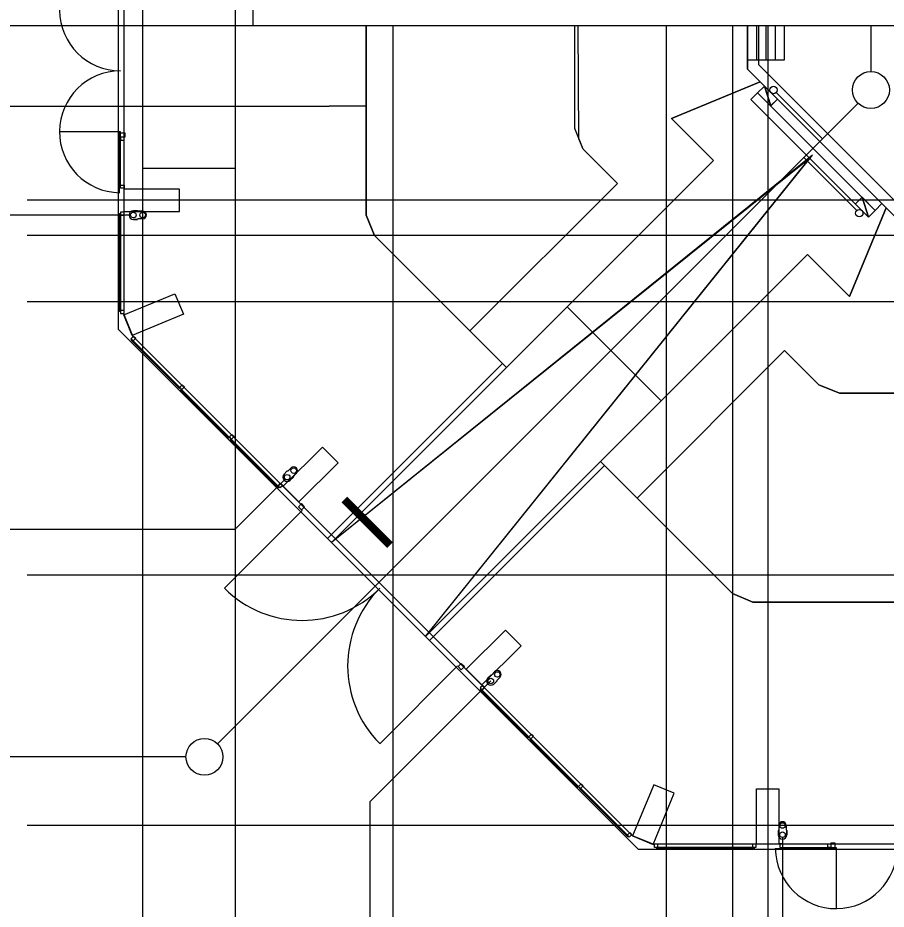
# Model space of a CAD drawing. Extents: x -264205 to -263659, y -1242401 to -1241986.
# Drawn here: x -263911.77 to -263888.26, y -1242243.07 to -1242218.94 of the extents above; entities that cross this region are included whole.
import ezdxf

# ---------------------------------------------------------------- set-up
doc = ezdxf.new("R2010")
doc.units = 0
for name, color, linetype in [('HESCON_OSI_STAVBY_KFA', 7, 'Continuous'), ('PROJEKT_OBRUBNIKY_KOMUNIKACIE', 7, 'Continuous'), ('RAM_NA_TLAC_2-1_1-250', 7, 'Continuous'), ('RAM_NA_TLAC_2-3_1-250', 7, 'Continuous'), ('SITUACIA_DSP_2D', 7, 'Continuous')]:
    doc.layers.add(name, color=color, linetype=linetype)

msp = doc.modelspace()

# ---------------------------------------------------------------- linework, layer by layer
at = {"layer": 'HESCON_OSI_STAVBY_KFA'}
for p, q in [((-263908.393, -1242083.237), (-263908.393, -1242246.707)), ((-263901.618, -1242219.157), (-263901.618, -1242246.707)), ((-263894.218, -1242219.157), (-263894.218, -1242246.707)), ((-263892.418, -1242219.157), (-263892.418, -1242246.707)), ((-263891.468, -1242219.157), (-263891.468, -1242246.707)), ((-263792.653, -1242223.882), (-263911.523, -1242223.882)), ((-263792.653, -1242224.832), (-263911.523, -1242224.832)), ((-263792.653, -1242226.632), (-263911.523, -1242226.632)), ((-263792.653, -1242234.032), (-263911.523, -1242234.032)), ((-263792.653, -1242240.807), (-263911.523, -1242240.807))]:
    msp.add_line(p, q, dxfattribs=at)
at = {"layer": 'PROJEKT_OBRUBNIKY_KOMUNIKACIE'}
for points in [[(-263794.893, -1242227.382), (-263808.968, -1242241.457), (-263894.968, -1242241.457), (-263909.043, -1242227.382), (-263909.043, -1242196.333), (-263914.143, -1242196.333), (-263914.143, -1242132.433), (-263909.043, -1242132.433), (-263909.043, -1242101.382), (-263894.968, -1242087.307), (-263808.968, -1242087.307), (-263794.893, -1242101.382), (-263794.893, -1242227.382)], [(-263898.543, -1242228.407), (-263902.112, -1242224.837), (-263902.343, -1242224.282), (-263902.343, -1242219.157)], [(-263891.673, -1242220.675), (-263894.073, -1242221.669), (-263892.937, -1242222.806), (-263898.544, -1242228.407)], [(-263895.995, -1242230.956), (-263890.391, -1242225.352), (-263889.254, -1242226.488), (-263888.26, -1242224.088), (-263891.673, -1242220.675)], [(-263903.277, -1242233.148), (-263900.731, -1242235.694), (-263890.254, -1242222.659), (-263903.277, -1242233.148)], [(-263898.65, -1242228.301), (-263903.39, -1242233.035), (-263900.629, -1242235.796), (-263895.875, -1242231.049)], [(-263898.544, -1242228.407), (-263903.281, -1242233.144), (-263900.731, -1242235.694), (-263895.982, -1242230.943)], [(-263807.941, -1242230.956), (-263811.512, -1242234.526), (-263812.068, -1242234.757), (-263891.868, -1242234.757), (-263892.424, -1242234.526), (-263895.994, -1242230.956)]]:
    msp.add_lwpolyline(points, dxfattribs=at)
at = {"layer": 'RAM_NA_TLAC_2-1_1-250'}
msp.add_line((-263905.413, -1242216.657), (-263905.413, -1242219.157), dxfattribs=at)
msp.add_lwpolyline([(-264147.913, -1242144.907), (-263857.913, -1242144.907), (-263857.913, -1242219.157), (-264147.913, -1242219.157)], close=True, dxfattribs=at)
at = {"layer": 'RAM_NA_TLAC_2-3_1-250'}
msp.add_line((-263908.389, -1242223.011), (-263905.889, -1242223.011), dxfattribs=at)
msp.add_lwpolyline([(-263980.139, -1242275.511), (-263980.139, -1241985.511), (-263905.889, -1241985.511), (-263905.889, -1242275.511)], close=True, dxfattribs=at)
at = {"layer": 'SITUACIA_DSP_2D'}
for p, q in [((-263909.043, -1242227.382), (-263909.043, -1242196.333)), ((-263908.893, -1242226.995), (-263908.893, -1242203.332)), ((-263902.343, -1242219.157), (-263902.343, -1242224.282)), ((-263902.343, -1242219.157), (-263902.343, -1242224.282)), ((-263902.343, -1242224.282), (-263902.343, -1242219.157)), ((-263896.693, -1242221.942), (-263896.693, -1242219.157)), ((-263896.578, -1242222.219), (-263896.603, -1242219.157)), ((-263892.018, -1242220.33), (-263892.018, -1242219.157)), ((-263892.018, -1242219.157), (-263892.018, -1242220.33)), ((-263891.768, -1242219.157), (-263891.768, -1242220.091)), ((-263891.718, -1242219.157), (-263891.718, -1242220.206)), ((-263891.518, -1242219.157), (-263891.518, -1242220.091)), ((-263891.268, -1242219.157), (-263891.268, -1242220.091)), ((-263891.018, -1242219.157), (-263891.018, -1242220.091)), ((-263888.673, -1242219.157), (-263888.673, -1242220.396)), ((-263891.018, -1242220.091), (-263892.018, -1242220.091)), ((-263891.718, -1242220.206), (-263887.792, -1242224.132)), ((-263891.673, -1242220.675), (-263892.018, -1242220.33)), ((-263892.018, -1242220.33), (-263887.916, -1242224.432)), ((-263894.073, -1242221.669), (-263891.673, -1242220.675)), ((-263891.673, -1242220.675), (-263894.073, -1242221.669)), ((-263888.26, -1242224.088), (-263891.673, -1242220.675)), ((-263891.742, -1242220.974), (-263891.558, -1242220.79)), ((-263891.558, -1242220.79), (-263891.204, -1242221.144)), ((-263888.376, -1242223.973), (-263891.558, -1242220.79)), ((-263891.387, -1242221.326), (-263891.558, -1242220.79)), ((-263891.924, -1242221.157), (-263891.74, -1242220.973)), ((-263891.924, -1242221.157), (-263888.742, -1242224.339)), ((-263888.558, -1242224.155), (-263891.74, -1242220.973)), ((-263891.388, -1242221.328), (-263891.204, -1242221.144)), ((-263891.24, -1242220.967), (-263889.988, -1242222.219)), ((-263923.393, -1242221.332), (-263903.343, -1242221.332)), ((-263889.023, -1242221.253), (-263906.365, -1242238.596)), ((-263902.343, -1242221.332), (-263903.343, -1242221.332)), ((-263892.937, -1242222.806), (-263894.073, -1242221.669)), ((-263894.073, -1242221.669), (-263892.937, -1242222.806)), ((-263908.993, -1242222.027), (-263910.643, -1242222.027)), ((-263909.018, -1242223.677), (-263909.018, -1242222.027)), ((-263908.993, -1242222.052), (-263908.993, -1242222.027)), ((-263908.993, -1242222.052), (-263908.873, -1242222.052)), ((-263908.993, -1242222.172), (-263908.993, -1242222.052)), ((-263908.873, -1242222.052), (-263908.873, -1242222.172)), ((-263896.463, -1242222.496), (-263896.693, -1242221.942)), ((-263909.018, -1242222.212), (-263909.018, -1242223.512)), ((-263908.993, -1242222.212), (-263909.018, -1242222.212)), ((-263908.893, -1242222.172), (-263908.993, -1242222.172)), ((-263908.993, -1242222.172), (-263908.993, -1242222.212)), ((-263908.873, -1242222.172), (-263908.993, -1242222.172)), ((-263908.993, -1242223.512), (-263908.993, -1242222.212)), ((-263908.993, -1242222.212), (-263908.993, -1242222.252)), ((-263908.993, -1242222.252), (-263908.893, -1242222.252)), ((-263908.893, -1242222.252), (-263908.893, -1242222.172)), ((-263896.463, -1242222.496), (-263896.578, -1242222.219)), ((-263895.535, -1242223.424), (-263896.463, -1242222.496)), ((-263895.535, -1242223.424), (-263896.463, -1242222.496)), ((-263890.333, -1242222.748), (-263903.277, -1242233.148)), ((-263900.731, -1242235.694), (-263890.333, -1242222.748)), ((-263892.937, -1242222.806), (-263898.544, -1242228.407)), ((-263896.896, -1242226.765), (-263892.937, -1242222.806)), ((-263889.059, -1242224.16), (-263890.494, -1242222.725)), ((-263909.018, -1242223.512), (-263908.993, -1242223.512)), ((-263908.993, -1242223.512), (-263908.993, -1242223.472)), ((-263908.993, -1242223.472), (-263908.893, -1242223.472)), ((-263908.993, -1242223.552), (-263908.993, -1242223.512)), ((-263908.893, -1242223.552), (-263908.993, -1242223.552)), ((-263907.398, -1242223.582), (-263908.898, -1242223.582)), ((-263908.898, -1242223.582), (-263908.898, -1242224.182)), ((-263908.893, -1242223.472), (-263908.893, -1242223.552)), ((-263907.398, -1242224.182), (-263907.398, -1242223.582)), ((-263899.53, -1242227.419), (-263895.535, -1242223.424)), ((-263899.53, -1242227.419), (-263895.535, -1242223.424)), ((-263889.096, -1242223.985), (-263888.912, -1242223.801)), ((-263888.742, -1242224.339), (-263888.912, -1242223.801)), ((-263888.26, -1242224.088), (-263889.254, -1242226.488)), ((-263889.254, -1242226.488), (-263888.26, -1242224.088)), ((-263888.56, -1242224.156), (-263888.376, -1242223.973)), ((-263908.718, -1242224.282), (-263918.67, -1242224.282)), ((-263909.018, -1242226.892), (-263909.018, -1242224.242)), ((-263909.018, -1242224.242), (-263908.993, -1242224.242)), ((-263908.893, -1242224.202), (-263908.993, -1242224.202)), ((-263908.993, -1242224.202), (-263908.993, -1242224.242)), ((-263908.993, -1242224.242), (-263908.993, -1242226.892)), ((-263908.993, -1242224.242), (-263908.993, -1242224.282)), ((-263908.993, -1242224.282), (-263908.893, -1242224.282)), ((-263908.898, -1242224.182), (-263907.398, -1242224.182)), ((-263908.893, -1242224.282), (-263908.893, -1242224.202)), ((-263908.532, -1242224.165), (-263908.643, -1242224.165)), ((-263908.518, -1242224.179), (-263908.532, -1242224.165)), ((-263908.393, -1242224.179), (-263908.518, -1242224.179)), ((-263902.343, -1242224.282), (-263902.113, -1242224.837)), ((-263902.343, -1242224.282), (-263902.113, -1242224.837)), ((-263902.112, -1242224.837), (-263902.343, -1242224.282)), ((-263888.742, -1242224.339), (-263888.558, -1242224.155)), ((-263908.643, -1242224.399), (-263908.532, -1242224.399)), ((-263908.532, -1242224.399), (-263908.643, -1242224.399)), ((-263908.518, -1242224.385), (-263908.532, -1242224.399)), ((-263908.393, -1242224.385), (-263908.518, -1242224.385)), ((-263902.113, -1242224.837), (-263899.53, -1242227.419)), ((-263902.113, -1242224.837), (-263899.53, -1242227.419)), ((-263898.543, -1242228.407), (-263902.112, -1242224.837)), ((-263895.995, -1242230.956), (-263890.391, -1242225.352)), ((-263890.391, -1242225.351), (-263894.351, -1242229.311)), ((-263889.254, -1242226.488), (-263890.391, -1242225.351)), ((-263890.391, -1242225.352), (-263889.254, -1242226.488)), ((-263908.903, -1242226.985), (-263907.518, -1242226.411)), ((-263907.518, -1242226.411), (-263907.288, -1242226.966)), ((-263908.993, -1242226.892), (-263909.018, -1242226.892)), ((-263908.893, -1242226.865), (-263908.993, -1242226.865)), ((-263908.993, -1242226.865), (-263908.993, -1242226.905)), ((-263908.993, -1242226.905), (-263908.993, -1242226.945)), ((-263908.993, -1242226.945), (-263908.893, -1242226.945)), ((-263908.674, -1242227.54), (-263908.903, -1242226.985)), ((-263908.893, -1242226.945), (-263908.893, -1242226.865)), ((-263907.288, -1242226.966), (-263908.674, -1242227.54)), ((-263894.351, -1242229.311), (-263896.896, -1242226.765)), ((-263908.893, -1242226.995), (-263908.663, -1242227.55)), ((-263894.968, -1242241.457), (-263909.043, -1242227.382)), ((-263908.709, -1242227.631), (-263908.638, -1242227.56)), ((-263908.68, -1242227.659), (-263908.709, -1242227.631)), ((-263908.685, -1242227.654), (-263908.703, -1242227.672)), ((-263908.703, -1242227.672), (-263907.395, -1242228.98)), ((-263907.377, -1242228.963), (-263908.685, -1242227.654)), ((-263908.652, -1242227.688), (-263908.68, -1242227.659)), ((-263908.663, -1242227.55), (-263895.135, -1242241.078)), ((-263908.581, -1242227.617), (-263908.652, -1242227.688)), ((-263908.638, -1242227.56), (-263908.581, -1242227.617)), ((-263895.005, -1242231.945), (-263891.01, -1242227.95)), ((-263891.01, -1242227.95), (-263895.005, -1242231.945)), ((-263891.01, -1242227.95), (-263890.082, -1242228.878)), ((-263890.082, -1242228.878), (-263891.01, -1242227.95)), ((-263898.65, -1242228.301), (-263903.39, -1242233.035)), ((-263898.544, -1242228.407), (-263903.281, -1242233.144)), ((-263907.39, -1242228.95), (-263907.319, -1242228.879)), ((-263907.319, -1242228.879), (-263907.262, -1242228.936)), ((-263890.082, -1242228.878), (-263889.528, -1242229.107)), ((-263889.528, -1242229.107), (-263890.082, -1242228.878)), ((-263907.395, -1242228.98), (-263907.377, -1242228.963)), ((-263907.361, -1242228.978), (-263907.39, -1242228.95)), ((-263907.363, -1242229.012), (-263907.345, -1242228.994)), ((-263906.055, -1242230.32), (-263907.363, -1242229.012)), ((-263907.333, -1242229.007), (-263907.361, -1242228.978)), ((-263907.345, -1242228.994), (-263906.037, -1242230.303)), ((-263907.262, -1242228.936), (-263907.333, -1242229.007)), ((-263889.528, -1242229.107), (-263874.98, -1242229.107)), ((-263874.98, -1242229.107), (-263889.528, -1242229.107)), ((-263906.037, -1242230.303), (-263906.055, -1242230.32)), ((-263906.046, -1242230.294), (-263905.975, -1242230.223)), ((-263906.017, -1242230.322), (-263906.046, -1242230.294)), ((-263906.019, -1242230.356), (-263906.001, -1242230.338)), ((-263904.711, -1242231.664), (-263906.019, -1242230.356)), ((-263905.989, -1242230.351), (-263906.017, -1242230.322)), ((-263906.001, -1242230.338), (-263904.693, -1242231.647)), ((-263905.918, -1242230.28), (-263905.989, -1242230.351)), ((-263905.975, -1242230.223), (-263905.918, -1242230.28)), ((-263903.526, -1242230.561), (-263904.586, -1242231.622)), ((-263903.101, -1242230.985), (-263903.526, -1242230.561)), ((-263904.162, -1242232.046), (-263903.101, -1242230.985)), ((-263900.731, -1242235.694), (-263895.982, -1242230.943)), ((-263900.629, -1242235.796), (-263895.875, -1242231.049)), ((-263892.424, -1242234.526), (-263895.994, -1242230.956)), ((-263904.484, -1242231.218), (-263904.563, -1242231.296)), ((-263904.465, -1242231.218), (-263904.484, -1242231.218)), ((-263904.376, -1242231.13), (-263904.465, -1242231.218)), ((-263904.231, -1242231.275), (-263904.319, -1242231.364)), ((-263904.533, -1242231.432), (-263905.894, -1242232.793)), ((-263904.726, -1242231.613), (-263904.656, -1242231.543)), ((-263904.656, -1242231.543), (-263904.599, -1242231.599)), ((-263904.397, -1242231.462), (-263904.319, -1242231.383)), ((-263904.319, -1242231.383), (-263904.397, -1242231.462)), ((-263904.319, -1242231.364), (-263904.319, -1242231.383)), ((-263904.698, -1242231.642), (-263904.726, -1242231.613)), ((-263904.693, -1242231.647), (-263904.711, -1242231.664)), ((-263904.67, -1242231.67), (-263904.698, -1242231.642)), ((-263904.599, -1242231.599), (-263904.67, -1242231.67)), ((-263904.586, -1242231.622), (-263904.162, -1242232.046)), ((-263892.422, -1242234.528), (-263895.005, -1242231.945)), ((-263895.005, -1242231.945), (-263892.422, -1242234.528)), ((-263904.074, -1242232.281), (-263906.177, -1242234.384)), ((-263904.091, -1242232.093), (-263904.176, -1242232.178)), ((-263904.176, -1242232.178), (-263904.091, -1242232.263)), ((-263904.006, -1242232.178), (-263904.091, -1242232.093)), ((-263904.091, -1242232.263), (-263904.006, -1242232.178)), ((-263904.091, -1242232.263), (-263904.074, -1242232.281)), ((-263905.894, -1242232.793), (-263918.643, -1242232.793)), ((-263903.39, -1242233.035), (-263900.629, -1242235.796)), ((-263903.281, -1242233.144), (-263900.731, -1242235.694)), ((-263903.277, -1242233.148), (-263900.731, -1242235.694)), ((-263891.868, -1242234.757), (-263892.424, -1242234.526)), ((-263891.868, -1242234.757), (-263892.422, -1242234.528)), ((-263892.422, -1242234.528), (-263891.868, -1242234.757)), ((-263874.98, -1242234.757), (-263891.868, -1242234.757)), ((-263891.868, -1242234.757), (-263874.98, -1242234.757)), ((-263812.068, -1242234.757), (-263891.868, -1242234.757)), ((-263899.631, -1242236.576), (-263898.571, -1242235.516)), ((-263898.571, -1242235.516), (-263898.147, -1242235.94)), ((-263898.147, -1242235.94), (-263899.207, -1242237.001)), ((-263899.866, -1242236.488), (-263901.97, -1242238.592)), ((-263899.849, -1242236.506), (-263899.764, -1242236.421)), ((-263899.764, -1242236.591), (-263899.849, -1242236.506)), ((-263899.764, -1242236.421), (-263899.679, -1242236.506)), ((-263899.679, -1242236.506), (-263899.764, -1242236.591)), ((-263899.207, -1242237.001), (-263899.631, -1242236.576)), ((-263898.969, -1242236.733), (-263899.047, -1242236.812)), ((-263898.949, -1242236.733), (-263898.969, -1242236.733)), ((-263898.861, -1242236.645), (-263898.949, -1242236.733)), ((-263898.715, -1242236.791), (-263898.804, -1242236.879)), ((-263898.804, -1242236.879), (-263898.804, -1242236.899)), ((-263898.965, -1242236.895), (-263902.238, -1242240.168)), ((-263899.018, -1242236.948), (-263902.238, -1242240.168)), ((-263899.185, -1242237.014), (-263899.255, -1242237.084)), ((-263899.255, -1242237.084), (-263899.227, -1242237.113)), ((-263899.232, -1242237.108), (-263899.25, -1242237.125)), ((-263897.924, -1242238.416), (-263899.232, -1242237.108)), ((-263899.227, -1242237.113), (-263899.199, -1242237.141)), ((-263899.199, -1242237.141), (-263899.128, -1242237.07)), ((-263899.128, -1242237.07), (-263899.185, -1242237.014)), ((-263898.804, -1242236.899), (-263898.882, -1242236.977)), ((-263898.882, -1242236.977), (-263898.804, -1242236.899)), ((-263899.25, -1242237.125), (-263897.942, -1242238.434)), ((-263897.942, -1242238.434), (-263897.924, -1242238.416)), ((-263897.865, -1242238.333), (-263897.936, -1242238.404)), ((-263897.936, -1242238.404), (-263897.908, -1242238.432)), ((-263897.908, -1242238.432), (-263897.88, -1242238.46)), ((-263897.888, -1242238.452), (-263897.906, -1242238.469)), ((-263897.906, -1242238.469), (-263896.598, -1242239.778)), ((-263896.58, -1242239.76), (-263897.888, -1242238.452)), ((-263897.88, -1242238.46), (-263897.809, -1242238.389)), ((-263897.809, -1242238.389), (-263897.865, -1242238.333)), ((-263907.219, -1242238.949), (-263926.43, -1242238.949)), ((-263896.598, -1242239.778), (-263896.58, -1242239.76)), ((-263896.522, -1242239.677), (-263896.592, -1242239.748)), ((-263896.592, -1242239.748), (-263896.564, -1242239.776)), ((-263896.564, -1242239.776), (-263896.536, -1242239.804)), ((-263896.536, -1242239.804), (-263896.465, -1242239.733)), ((-263896.465, -1242239.733), (-263896.522, -1242239.677)), ((-263894.551, -1242239.702), (-263895.125, -1242241.088)), ((-263893.997, -1242239.932), (-263894.551, -1242239.702)), ((-263896.566, -1242239.809), (-263896.548, -1242239.792)), ((-263895.258, -1242241.118), (-263896.566, -1242239.809)), ((-263896.548, -1242239.792), (-263895.24, -1242241.1)), ((-263894.571, -1242241.318), (-263893.997, -1242239.932)), ((-263891.768, -1242241.312), (-263891.768, -1242239.812)), ((-263891.768, -1242239.812), (-263891.168, -1242239.812)), ((-263891.168, -1242239.812), (-263891.168, -1242241.312)), ((-263902.238, -1242240.168), (-263902.238, -1242252.949)), ((-263891.171, -1242240.932), (-263891.185, -1242240.946)), ((-263891.185, -1242240.946), (-263891.185, -1242241.057)), ((-263891.171, -1242240.807), (-263891.171, -1242240.932)), ((-263890.965, -1242240.807), (-263890.965, -1242240.932)), ((-263890.965, -1242240.932), (-263890.951, -1242240.946)), ((-263890.951, -1242241.057), (-263890.951, -1242240.946)), ((-263890.951, -1242240.946), (-263890.951, -1242241.057)), ((-263895.202, -1242240.996), (-263895.273, -1242241.067)), ((-263895.273, -1242241.067), (-263895.245, -1242241.095)), ((-263895.24, -1242241.1), (-263895.258, -1242241.118)), ((-263895.245, -1242241.095), (-263895.216, -1242241.123)), ((-263895.216, -1242241.123), (-263895.146, -1242241.053)), ((-263895.146, -1242241.053), (-263895.202, -1242240.996)), ((-263895.135, -1242241.078), (-263894.581, -1242241.307)), ((-263895.125, -1242241.088), (-263894.571, -1242241.318)), ((-263891.068, -1242241.132), (-263891.068, -1242253.353)), ((-263808.968, -1242241.457), (-263894.968, -1242241.457)), ((-263894.581, -1242241.307), (-263809.355, -1242241.307)), ((-263894.531, -1242241.407), (-263894.531, -1242241.307)), ((-263894.531, -1242241.307), (-263894.451, -1242241.307)), ((-263894.491, -1242241.407), (-263894.531, -1242241.407)), ((-263894.451, -1242241.407), (-263894.491, -1242241.407)), ((-263891.828, -1242241.407), (-263894.478, -1242241.407)), ((-263894.478, -1242241.407), (-263894.478, -1242241.432)), ((-263894.478, -1242241.432), (-263891.828, -1242241.432)), ((-263894.451, -1242241.307), (-263894.451, -1242241.407)), ((-263891.868, -1242241.407), (-263891.868, -1242241.307)), ((-263891.868, -1242241.307), (-263891.788, -1242241.307)), ((-263891.828, -1242241.407), (-263891.868, -1242241.407)), ((-263891.828, -1242241.432), (-263891.828, -1242241.407)), ((-263891.788, -1242241.407), (-263891.828, -1242241.407)), ((-263891.788, -1242241.307), (-263891.788, -1242241.407)), ((-263891.168, -1242241.312), (-263891.768, -1242241.312)), ((-263891.263, -1242241.432), (-263889.613, -1242241.432)), ((-263891.058, -1242241.307), (-263891.138, -1242241.307)), ((-263891.138, -1242241.307), (-263891.138, -1242241.407)), ((-263891.138, -1242241.407), (-263891.098, -1242241.407)), ((-263891.098, -1242241.432), (-263891.098, -1242241.407)), ((-263891.098, -1242241.407), (-263889.798, -1242241.407)), ((-263891.098, -1242241.407), (-263891.058, -1242241.407)), ((-263889.798, -1242241.432), (-263891.098, -1242241.432)), ((-263891.058, -1242241.407), (-263891.058, -1242241.307)), ((-263889.838, -1242241.407), (-263889.838, -1242241.307)), ((-263889.838, -1242241.307), (-263889.758, -1242241.307)), ((-263889.798, -1242241.407), (-263889.838, -1242241.407)), ((-263889.798, -1242241.407), (-263889.798, -1242241.432)), ((-263889.758, -1242241.407), (-263889.798, -1242241.407)), ((-263889.638, -1242241.287), (-263889.758, -1242241.287)), ((-263889.758, -1242241.287), (-263889.758, -1242241.407)), ((-263889.758, -1242241.307), (-263889.758, -1242241.407)), ((-263889.758, -1242241.407), (-263889.638, -1242241.407)), ((-263889.638, -1242241.407), (-263889.638, -1242241.287)), ((-263889.638, -1242241.407), (-263889.613, -1242241.407)), ((-263889.613, -1242241.407), (-263889.613, -1242243.057))]:
    msp.add_line(p, q, dxfattribs=at)
for points in [[(-263891.558, -1242220.79), (-263891.387, -1242221.326), (-263891.204, -1242221.144)], [(-263888.742, -1242224.339), (-263888.558, -1242224.155), (-263888.912, -1242223.801)]]:
    msp.add_lwpolyline(points, close=True, dxfattribs=at)
for centre, radius in [((-263888.673, -1242220.896), 0.5), ((-263891.31, -1242220.896), 0.1), ((-263908.643, -1242224.282), 0.075), ((-263908.393, -1242224.282), 0.075), ((-263888.988, -1242224.231), 0.1), ((-263904.48, -1242231.379), 0.075), ((-263904.303, -1242231.202), 0.075), ((-263898.965, -1242236.895), 0.075), ((-263898.788, -1242236.718), 0.075), ((-263906.719, -1242238.949), 0.5), ((-263891.068, -1242240.807), 0.075), ((-263891.068, -1242241.057), 0.075)]:
    msp.add_circle(centre, radius, dxfattribs=at)
for centre, radius, start, end in [((-263908.993, -1242218.727), 1.65, 90.8682, 270), ((-263908.993, -1242222.027), 1.65, 90, 269.1318), ((-263908.643, -1242224.282), 0.117, 90, 270), ((-263908.393, -1242224.282), 0.103, 270, 90), ((-263904.48, -1242231.379), 0.117, 135, 315), ((-263904.303, -1242231.202), 0.103, 315, 135), ((-263904.074, -1242232.281), 2.975, 225.0001, 315.0001), ((-263899.866, -1242236.488), 2.975, 134.9999, 224.9999), ((-263898.788, -1242236.718), 0.103, 315, 135), ((-263898.965, -1242236.895), 0.117, 135, 315), ((-263891.068, -1242240.807), 0.103, 360, 180), ((-263891.068, -1242241.057), 0.117, 180, 360), ((-263889.613, -1242241.407), 1.65, 180.8682, 0)]:
    msp.add_arc(centre, radius, start, end, dxfattribs=at)

# ---------------------------------------------------------------- texts
msp.add_text('I', height=1.75, rotation=45.0119, dxfattribs=at).set_placement((-263901.924, -1242233.448))

doc.saveas('drawing.dxf')
